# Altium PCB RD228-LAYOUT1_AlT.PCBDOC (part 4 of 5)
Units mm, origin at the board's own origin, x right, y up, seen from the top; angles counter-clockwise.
Board outline 130 x 73 mm, 4 copper layers (TOP, Mid-Layer 1, Mid-Layer 2, BOTTOM), stack 0.711 mm thick; 225 components, 171 nets, 818 pads, 538 vias.
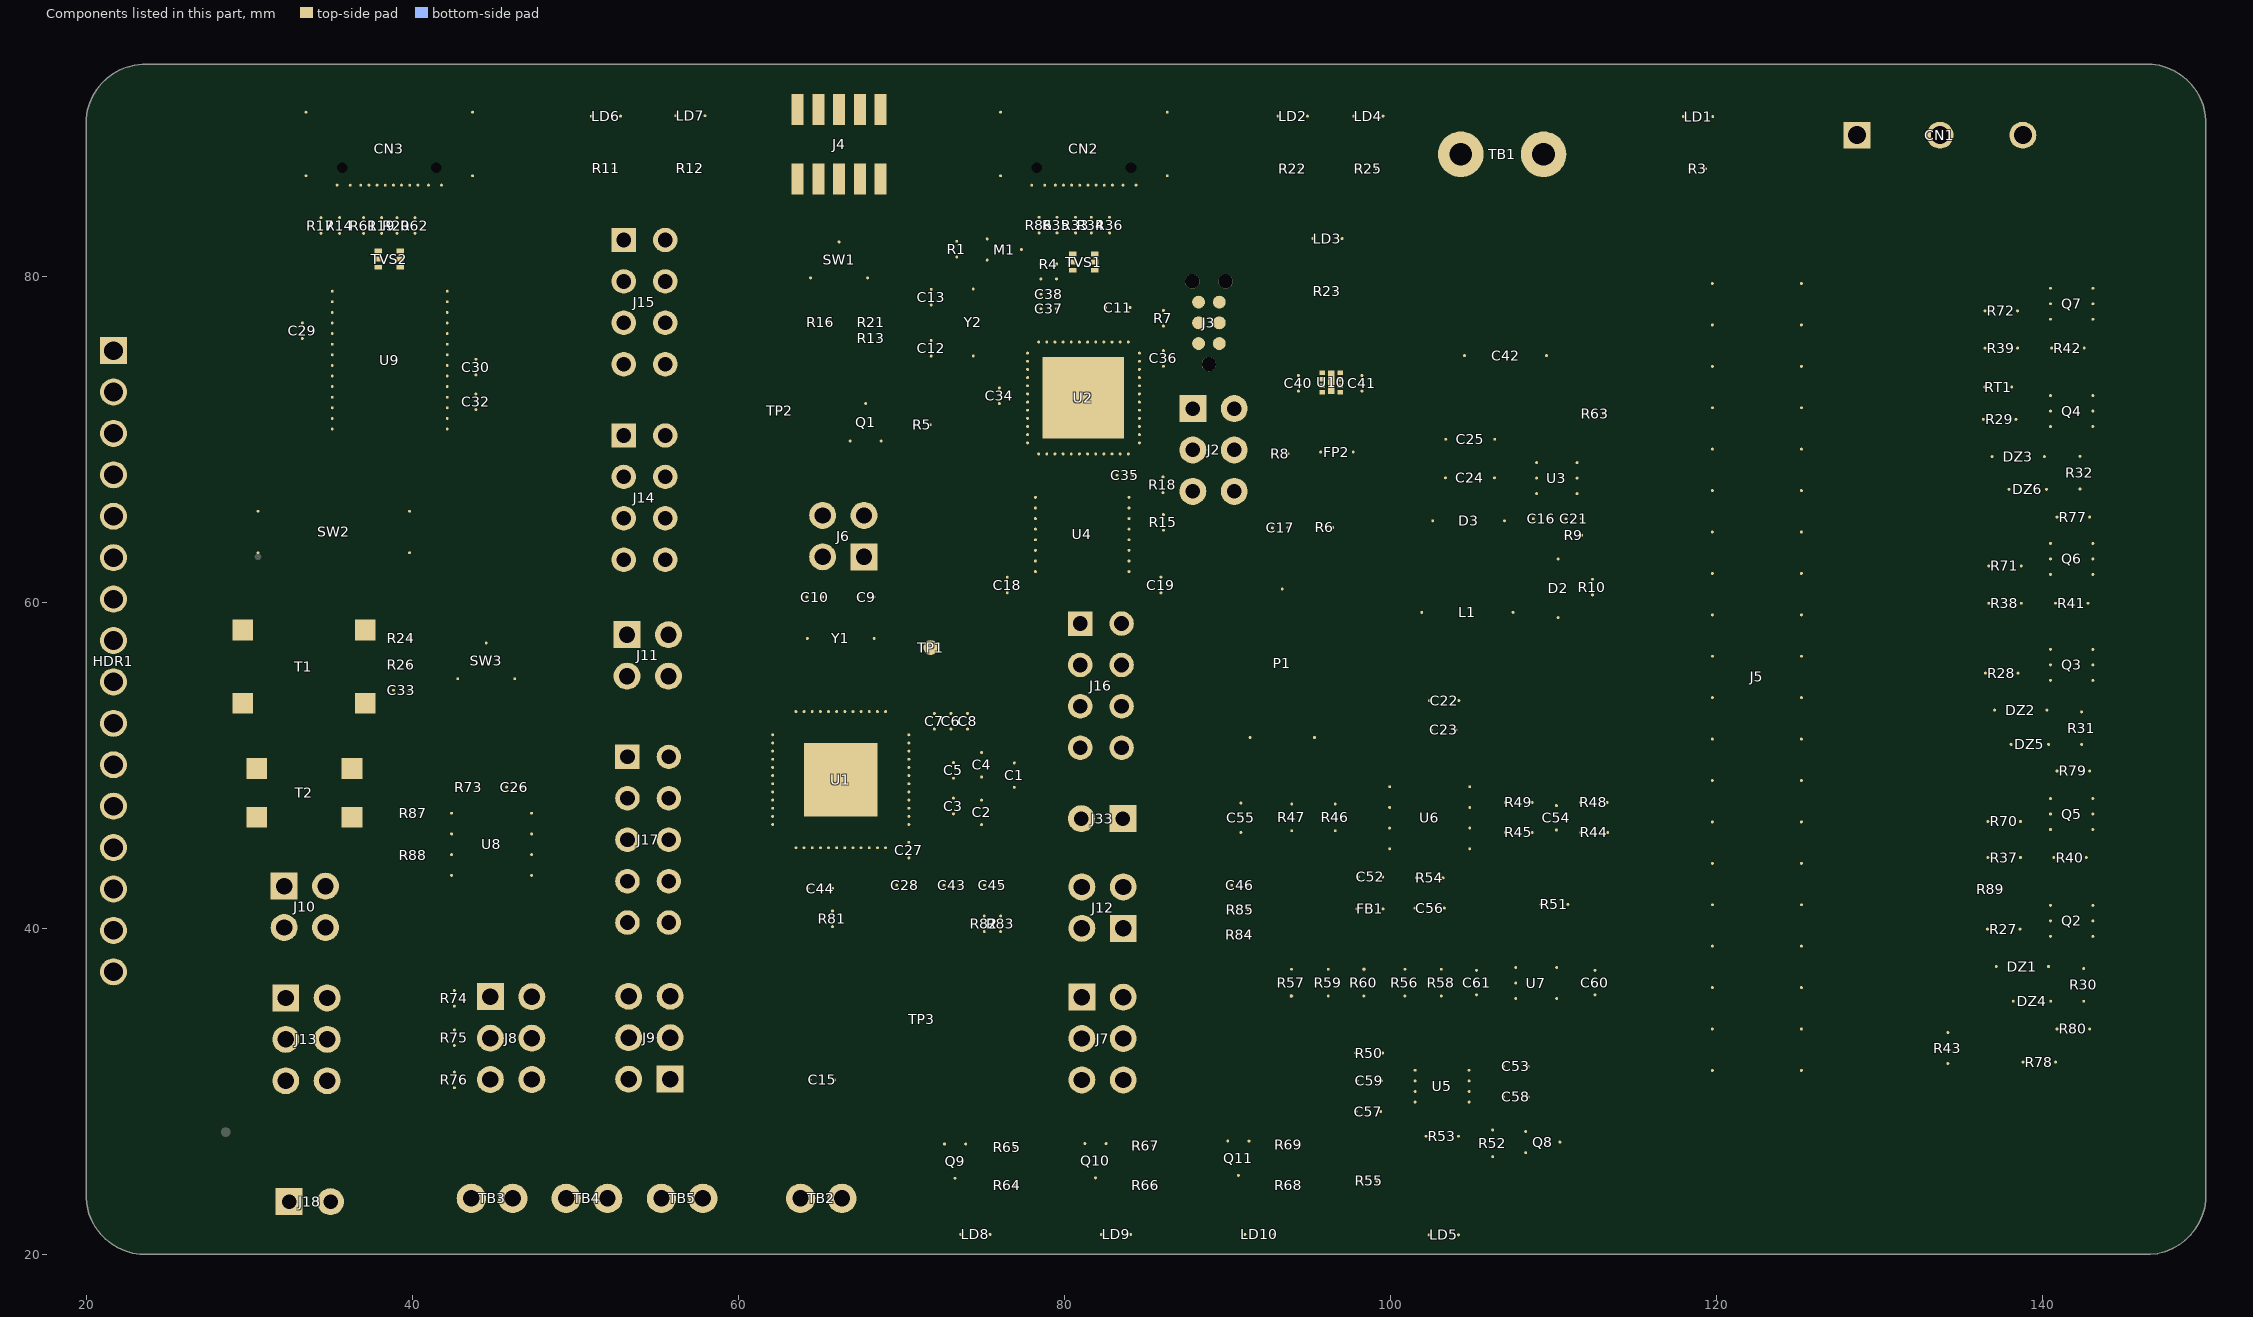
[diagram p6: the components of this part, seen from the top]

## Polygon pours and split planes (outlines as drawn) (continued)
no net on Top Overlay "TOPOVERLAY694" (solid, pour order 0): 274 vertices, not listed, extent 97.347,26.775 98.21,27.784
no net on Top Overlay "TOPOVERLAY693" (solid, pour order 0): 200 vertices, not listed, extent 98.32,26.775 98.968,27.755
no net on Top Overlay "TOPOVERLAY692" (solid, pour order 0): 94 vertices, not listed, extent 99.087,26.791 99.719,27.755
no net on Top Overlay "TOPOVERLAY691" (solid, pour order 0): 220 vertices, not listed, extent 98.149,34.039 98.793,35.035
no net on Top Overlay "TOPOVERLAY690" (solid, pour order 0): 151 vertices, not listed, extent 98.912,34.039 99.548,35.035
no net on Top Overlay "TOPOVERLAY689" (solid, pour order 0): 119 vertices, not listed, extent 97.22,34.055 98.078,35.032
no net on Top Overlay "TOPOVERLAY688" (solid, pour order 0): 274 vertices, not listed, extent 96.975,71.355 97.838,72.365
no net on Top Overlay "TOPOVERLAY687" (solid, pour order 0): 98.333,71.371 98.333,71.604 97.909,71.604 97.909,71.714 98.355,72.347 98.453,72.347 98.453,71.714 98.584,71.714 98.584,71.604 98.453,71.604 98.453,71.371
no net on Top Overlay "TOPOVERLAY686" (solid, pour order 0): 48 vertices, not listed, extent 98.799,71.371 99.158,72.351
no net on Top Overlay "TOPOVERLAY685" (solid, pour order 0): 274 vertices, not listed, extent 96.864,87.554 97.87,88.731
no net on Top Overlay "TOPOVERLAY684" (solid, pour order 0): 42 vertices, not listed, extent 99.287,87.573 100.375,88.711
no net on Top Overlay "TOPOVERLAY683" (solid, pour order 0): 165 vertices, not listed, extent 98.01,87.554 99.099,88.731
no net on Top Overlay "TOPOVERLAY682" (solid, pour order 0): 216 vertices, not listed, extent 97.292,67.075 97.937,68.055
no net on Top Overlay "TOPOVERLAY681" (solid, pour order 0): 95.62,67.075 95.62,68.052 96.279,68.052 96.279,67.936 95.749,67.936 95.749,67.634 96.207,67.634 96.207,67.519 95.749,67.519 95.749,67.075
no net on Top Overlay "TOPOVERLAY680" (solid, pour order 0): 75 vertices, not listed, extent 96.446,67.075 97.192,68.052
no net on Top Overlay "TOPOVERLAY679" (solid, pour order 0): 220 vertices, not listed, extent 97.154,48.415 97.799,49.412
no net on Top Overlay "TOPOVERLAY678" (solid, pour order 0): 119 vertices, not listed, extent 95.467,48.432 96.325,49.408
no net on Top Overlay "TOPOVERLAY677" (solid, pour order 0): 96.786,48.432 96.786,48.665 96.362,48.665 96.362,48.775 96.807,49.408 96.906,49.408 96.906,48.775 97.037,48.775 97.037,48.665 96.906,48.665 96.906,48.432
no net on Top Overlay "TOPOVERLAY676" (solid, pour order 0): 220 vertices, not listed, extent 96.117,65.129 96.761,66.125
no net on Top Overlay "TOPOVERLAY675" (solid, pour order 0): 119 vertices, not listed, extent 95.188,65.145 96.046,66.121
no net on Top Overlay "TOPOVERLAY674" (solid, pour order 0): 148 vertices, not listed, extent 95.162,74.628 95.93,75.621
no net on Top Overlay "TOPOVERLAY673" (solid, pour order 0): 151 vertices, not listed, extent 96.854,74.628 97.49,75.625
no net on Top Overlay "TOPOVERLAY672" (solid, pour order 0): 48 vertices, not listed, extent 96.188,74.644 96.547,75.625
no net on Top Overlay "TOPOVERLAY671" (solid, pour order 0): 241 vertices, not listed, extent 96.753,38.306 97.395,39.303
no net on Top Overlay "TOPOVERLAY670" (solid, pour order 0): 119 vertices, not listed, extent 95.061,38.322 95.919,39.299
no net on Top Overlay "TOPOVERLAY669" (solid, pour order 0): 200 vertices, not listed, extent 95.994,38.306 96.642,39.286
no net on Top Overlay "TOPOVERLAY668" (solid, pour order 0): 312 vertices, not listed, extent 96.652,77.524 97.291,78.521
no net on Top Overlay "TOPOVERLAY667" (solid, pour order 0): 119 vertices, not listed, extent 94.959,77.54 95.817,78.517
no net on Top Overlay "TOPOVERLAY666" (solid, pour order 0): 216 vertices, not listed, extent 95.877,77.54 96.522,78.521
no net on Top Overlay "TOPOVERLAY665" (solid, pour order 0): 48 vertices, not listed, extent 96.714,40.685 97.073,41.665
no net on Top Overlay "TOPOVERLAY664" (solid, pour order 0): 94.934,40.685 94.934,41.661 95.593,41.661 95.593,41.546 95.063,41.546 95.063,41.244 95.522,41.244 95.522,41.129 95.063,41.129 95.063,40.685
no net on Top Overlay "TOPOVERLAY663" (solid, pour order 0): 117 vertices, not listed, extent 95.756,40.685 96.493,41.661
no net on Top Overlay "TOPOVERLAY662" (solid, pour order 0): 274 vertices, not listed, extent 94.807,42.573 95.67,43.583
no net on Top Overlay "TOPOVERLAY661" (solid, pour order 0): 200 vertices, not listed, extent 95.78,42.573 96.428,43.554
no net on Top Overlay "TOPOVERLAY660" (solid, pour order 0): 216 vertices, not listed, extent 96.523,42.59 97.168,43.57
no net on Top Overlay "TOPOVERLAY659" (solid, pour order 0): 312 vertices, not listed, extent 94.731,80.201 95.37,81.197
no net on Top Overlay "TOPOVERLAY658" (solid, pour order 0): 312 vertices, not listed, extent 95.868,80.201 96.507,81.197
no net on Top Overlay "TOPOVERLAY657" (solid, pour order 0): 95.556,80.217 95.556,80.353 95.692,80.353 95.692,80.217
no net on Top Overlay "TOPOVERLAY656" (solid, pour order 0): 30 vertices, not listed, extent 96.575,80.217 97.468,81.194
no net on Top Overlay "TOPOVERLAY655" (solid, pour order 0): 200 vertices, not listed, extent 95.656,31.88 96.304,32.86
no net on Top Overlay "TOPOVERLAY654" (solid, pour order 0): 151 vertices, not listed, extent 96.415,31.88 97.051,32.876
no net on Top Overlay "TOPOVERLAY653" (solid, pour order 0): 119 vertices, not listed, extent 94.723,31.896 95.581,32.873
no net on Top Overlay "TOPOVERLAY652" (solid, pour order 0): 274 vertices, not listed, extent 94.68,30.178 95.543,31.188
no net on Top Overlay "TOPOVERLAY651" (solid, pour order 0): 200 vertices, not listed, extent 95.653,30.178 96.301,31.158
no net on Top Overlay "TOPOVERLAY650" (solid, pour order 0): 241 vertices, not listed, extent 96.412,30.178 97.054,31.175
no net on Top Overlay "TOPOVERLAY649" (solid, pour order 0): 274 vertices, not listed, extent 93.029,71.352 93.892,72.361
no net on Top Overlay "TOPOVERLAY648" (solid, pour order 0): 151 vertices, not listed, extent 94.761,71.352 95.397,72.348
no net on Top Overlay "TOPOVERLAY647" (solid, pour order 0): 94.387,71.368 94.387,71.601 93.963,71.601 93.963,71.711 94.409,72.344 94.507,72.344 94.507,71.711 94.639,71.711 94.639,71.601 94.507,71.601 94.507,71.368
no net on Top Overlay "TOPOVERLAY646" (solid, pour order 0): 216 vertices, not listed, extent 94.553,85.058 95.198,86.039
no net on Top Overlay "TOPOVERLAY645" (solid, pour order 0): 119 vertices, not listed, extent 92.876,85.058 93.735,86.035
no net on Top Overlay "TOPOVERLAY644" (solid, pour order 0): 216 vertices, not listed, extent 93.795,85.058 94.44,86.039
no net on Top Overlay "TOPOVERLAY643" (solid, pour order 0): 94 vertices, not listed, extent 94.5,44.266 95.132,45.23
no net on Top Overlay "TOPOVERLAY642" (solid, pour order 0): 119 vertices, not listed, extent 92.8,44.266 93.658,45.242
no net on Top Overlay "TOPOVERLAY641" (solid, pour order 0): 94.119,44.266 94.119,44.499 93.695,44.499 93.695,44.609 94.14,45.242 94.239,45.242 94.239,44.609 94.37,44.609 94.37,44.499 94.239,44.499 94.239,44.266
no net on Top Overlay "TOPOVERLAY640" (solid, pour order 0): 200 vertices, not listed, extent 93.658,34.064 94.305,35.045
no net on Top Overlay "TOPOVERLAY639" (solid, pour order 0): 119 vertices, not listed, extent 92.724,34.081 93.582,35.057
no net on Top Overlay "TOPOVERLAY638" (solid, pour order 0): 94 vertices, not listed, extent 94.424,34.081 95.056,35.045
no net on Top Overlay "TOPOVERLAY637" (solid, pour order 0): 220 vertices, not listed, extent 93.554,27.257 94.199,28.254
no net on Top Overlay "TOPOVERLAY636" (solid, pour order 0): 119 vertices, not listed, extent 92.625,27.273 93.483,28.25
no net on Top Overlay "TOPOVERLAY635" (solid, pour order 0): 241 vertices, not listed, extent 94.317,27.257 94.959,28.254
no net on Top Overlay "TOPOVERLAY634" (solid, pour order 0): 48 vertices, not listed, extent 93.576,62.63 93.935,63.61
no net on Top Overlay "TOPOVERLAY633" (solid, pour order 0): 75 vertices, not listed, extent 92.622,62.63 93.368,63.607
no net on Top Overlay "TOPOVERLAY632" (solid, pour order 0): 220 vertices, not listed, extent 93.551,24.87 94.196,25.866
no net on Top Overlay "TOPOVERLAY631" (solid, pour order 0): 203 vertices, not listed, extent 94.313,24.87 94.956,25.866
no net on Top Overlay "TOPOVERLAY630" (solid, pour order 0): 119 vertices, not listed, extent 92.622,24.886 93.481,25.862
no net on Top Overlay "TOPOVERLAY629" (solid, pour order 0): 203 vertices, not listed, extent 93.352,69.701 93.995,70.697
no net on Top Overlay "TOPOVERLAY628" (solid, pour order 0): 119 vertices, not listed, extent 92.419,69.717 93.277,70.693
no net on Top Overlay "TOPOVERLAY627" (solid, pour order 0): 94.696,87.548 94.696,88.685 94.85,88.685 95.449,87.792 95.449,88.685 95.593,88.685 95.593,87.548 95.437,87.548 94.84,88.44 94.84,87.548
no net on Top Overlay "TOPOVERLAY626" (solid, pour order 0): 119 vertices, not listed, extent 92.405,87.548 93.405,88.685
no net on Top Overlay "TOPOVERLAY625" (solid, pour order 0): 148 vertices, not listed, extent 93.553,87.529 94.447,88.685
no net on Top Overlay "TOPOVERLAY624" (solid, pour order 0): 274 vertices, not listed, extent 92.038,65.103 92.901,66.113
no net on Top Overlay "TOPOVERLAY623" (solid, pour order 0): 94 vertices, not listed, extent 93.779,65.119 94.41,66.083
no net on Top Overlay "TOPOVERLAY622" (solid, pour order 0): 48 vertices, not listed, extent 93.104,65.119 93.463,66.1
no net on Top Overlay "TOPOVERLAY621" (solid, pour order 0): 200 vertices, not listed, extent 93.578,40.643 94.225,41.623
no net on Top Overlay "TOPOVERLAY620" (solid, pour order 0): 203 vertices, not listed, extent 92.818,40.643 93.461,41.639
no net on Top Overlay "TOPOVERLAY619" (solid, pour order 0): 119 vertices, not listed, extent 91.886,40.659 92.744,41.636
no net on Top Overlay "TOPOVERLAY618" (solid, pour order 0): 312 vertices, not listed, extent 92.946,22.253 93.585,23.25
no net on Top Overlay "TOPOVERLAY617" (solid, pour order 0): 100 vertices, not listed, extent 92.009,22.27 92.817,23.246
no net on Top Overlay "TOPOVERLAY616" (solid, pour order 0): 90.336,22.27 90.336,23.246 90.466,23.246 90.466,22.385 90.946,22.385 90.946,22.27
no net on Top Overlay "TOPOVERLAY615" (solid, pour order 0): 91.102,22.27 91.102,23.246 91.808,23.246 91.808,23.131 91.232,23.131 91.232,22.833 91.772,22.833 91.772,22.717 91.232,22.717 91.232,22.385 91.831,22.385 91.831,22.27
no net on Top Overlay "TOPOVERLAY614" (solid, pour order 0): 203 vertices, not listed, extent 90.609,37.951 91.252,38.947
no net on Top Overlay "TOPOVERLAY613" (solid, pour order 0): 119 vertices, not listed, extent 89.676,37.967 90.534,38.943
no net on Top Overlay "TOPOVERLAY612" (solid, pour order 0): 91.753,37.967 91.753,38.2 91.329,38.2 91.329,38.31 91.774,38.943 91.873,38.943 91.873,38.31 92.004,38.31 92.004,38.2 91.873,38.2 91.873,37.967
no net on Top Overlay "TOPOVERLAY611" (solid, pour order 0): 274 vertices, not listed, extent 89.651,48.644 90.514,49.654
no net on Top Overlay "TOPOVERLAY610" (solid, pour order 0): 200 vertices, not listed, extent 91.382,48.644 92.03,49.624
no net on Top Overlay "TOPOVERLAY609" (solid, pour order 0): 200 vertices, not listed, extent 90.624,48.644 91.272,49.624
no net on Top Overlay "TOPOVERLAY608" (solid, pour order 0): 48 vertices, not listed, extent 91.458,27.781 91.817,28.762
no net on Top Overlay "TOPOVERLAY607" (solid, pour order 0): 202 vertices, not listed, extent 89.549,27.706 90.502,28.775
no net on Top Overlay "TOPOVERLAY606" (solid, pour order 0): 48 vertices, not listed, extent 90.7,27.781 91.059,28.762
no net on Top Overlay "TOPOVERLAY605" (solid, pour order 0): 220 vertices, not listed, extent 91.174,43.259 91.819,44.256
no net on Top Overlay "TOPOVERLAY604" (solid, pour order 0): 274 vertices, not listed, extent 89.447,43.259 90.31,44.269
no net on Top Overlay "TOPOVERLAY603" (solid, pour order 0): 90.806,43.275 90.806,43.509 90.382,43.509 90.382,43.618 90.828,44.252 90.926,44.252 90.926,43.618 91.057,43.618 91.057,43.509 90.926,43.509 90.926,43.275
no net on Top Overlay "TOPOVERLAY602" (solid, pour order 0): 110 vertices, not listed, extent 88.409,64.722 88.946,65.715
no net on Top Overlay "TOPOVERLAY601" (solid, pour order 0): 216 vertices, not listed, extent 89.093,64.738 89.738,65.719
no net on Top Overlay "TOPOVERLAY600" (solid, pour order 0): 312 vertices, not listed, extent 88.931,80.419 89.57,81.416
no net on Top Overlay "TOPOVERLAY599" (solid, pour order 0): 110 vertices, not listed, extent 88.231,80.419 88.768,81.412
no net on Top Overlay "TOPOVERLAY598" (solid, pour order 0): 295 vertices, not listed, extent 89.738,87.526 90.79,88.703
no net on Top Overlay "TOPOVERLAY597" (solid, pour order 0): 100 vertices, not listed, extent 87.568,87.545 88.509,88.683
no net on Top Overlay "TOPOVERLAY596" (solid, pour order 0): 117 vertices, not listed, extent 88.71,87.545 89.569,88.683
no net on Top Overlay "TOPOVERLAY595" (solid, pour order 0): 274 vertices, not listed, extent 87.625,40.541 88.488,41.551
no net on Top Overlay "TOPOVERLAY594" (solid, pour order 0): 75 vertices, not listed, extent 88.647,40.558 89.393,41.534
no net on Top Overlay "TOPOVERLAY593" (solid, pour order 0): 31 vertices, not listed, extent 86.653,40.558 87.547,41.534
no net on Top Overlay "TOPOVERLAY592" (solid, pour order 0): 274 vertices, not listed, extent 86.526,60.607 87.389,61.617
no net on Top Overlay "TOPOVERLAY591" (solid, pour order 0): 48 vertices, not listed, extent 87.592,60.624 87.951,61.604
no net on Top Overlay "TOPOVERLAY590" (solid, pour order 0): 241 vertices, not listed, extent 88.258,60.607 88.9,61.604
no net on Top Overlay "TOPOVERLAY589" (solid, pour order 0): 200 vertices, not listed, extent 87.101,62.868 87.748,63.848
no net on Top Overlay "TOPOVERLAY588" (solid, pour order 0): 119 vertices, not listed, extent 85.409,62.884 86.267,63.861
no net on Top Overlay "TOPOVERLAY587" (solid, pour order 0): 48 vertices, not listed, extent 86.435,62.884 86.794,63.864
no net on Top Overlay "TOPOVERLAY586" (solid, pour order 0): 48 vertices, not listed, extent 87.882,35.198 88.241,36.178
no net on Top Overlay "TOPOVERLAY585" (solid, pour order 0): 100 vertices, not listed, extent 86.853,35.198 87.661,36.175
no net on Top Overlay "TOPOVERLAY584" (solid, pour order 0): 85.18,35.198 85.18,36.175 85.31,36.175 85.31,35.313 85.79,35.313 85.79,35.198
no net on Top Overlay "TOPOVERLAY583" (solid, pour order 0): 85.946,35.198 85.946,36.175 86.652,36.175 86.652,36.059 86.076,36.059 86.076,35.761 86.616,35.761 86.616,35.646 86.076,35.646 86.076,35.313 86.675,35.313 86.675,35.198
no net on Top Overlay "TOPOVERLAY582" (solid, pour order 0): 216 vertices, not listed, extent 87.774,32.607 88.419,33.588
no net on Top Overlay "TOPOVERLAY581" (solid, pour order 0): 100 vertices, not listed, extent 86.853,32.607 87.661,33.584
no net on Top Overlay "TOPOVERLAY580" (solid, pour order 0): 85.18,32.607 85.18,33.584 85.31,33.584 85.31,32.723 85.79,32.723 85.79,32.607
no net on Top Overlay "TOPOVERLAY579" (solid, pour order 0): 85.946,32.607 85.946,33.584 86.652,33.584 86.652,33.469 86.076,33.469 86.076,33.17 86.616,33.17 86.616,33.055 86.076,33.055 86.076,32.723 86.675,32.723 86.675,32.607
no net on Top Overlay "TOPOVERLAY578" (solid, pour order 0): 312 vertices, not listed, extent 87.79,30.102 88.429,31.098
no net on Top Overlay "TOPOVERLAY577" (solid, pour order 0): 100 vertices, not listed, extent 86.853,30.118 87.661,31.095
no net on Top Overlay "TOPOVERLAY576" (solid, pour order 0): 85.18,30.118 85.18,31.095 85.31,31.095 85.31,30.233 85.79,30.233 85.79,30.118
no net on Top Overlay "TOPOVERLAY575" (solid, pour order 0): 85.946,30.118 85.946,31.095 86.652,31.095 86.652,30.979 86.076,30.979 86.076,30.681 86.616,30.681 86.616,30.566 86.076,30.566 86.076,30.233 86.675,30.233 86.675,30.118
no net on Top Overlay "TOPOVERLAY574" (solid, pour order 0): 42 vertices, not listed, extent 86.739,58.16 87.672,59.136
no net on Top Overlay "TOPOVERLAY573" (solid, pour order 0): 75 vertices, not listed, extent 87.879,58.16 88.625,59.136
no net on Top Overlay "TOPOVERLAY572" (solid, pour order 0): 85.248,58.16 85.248,59.021 84.926,59.021 84.926,59.136 85.701,59.136 85.701,59.021 85.378,59.021 85.378,58.16
no net on Top Overlay "TOPOVERLAY571" (solid, pour order 0): 85.836,58.16 85.836,59.136 86.542,59.136 86.542,59.021 85.965,59.021 85.965,58.723 86.506,58.723 86.506,58.608 85.965,58.608 85.965,58.275 86.565,58.275 86.565,58.16
no net on Top Overlay "TOPOVERLAY570" (solid, pour order 0): 87.146,55.62 87.146,56.481 86.824,56.481 86.824,56.596 87.598,56.596 87.598,56.481 87.275,56.481 87.275,55.62
no net on Top Overlay "TOPOVERLAY569" (solid, pour order 0): 165 vertices, not listed, extent 85.797,55.604 86.731,56.613
no net on Top Overlay "TOPOVERLAY568" (solid, pour order 0): 75 vertices, not listed, extent 84.926,55.62 85.672,56.596
no net on Top Overlay "TOPOVERLAY567" (solid, pour order 0): 42 vertices, not listed, extent 86.739,53.08 87.672,54.056
no net on Top Overlay "TOPOVERLAY566" (solid, pour order 0): 75 vertices, not listed, extent 87.879,53.08 88.625,54.056
no net on Top Overlay "TOPOVERLAY565" (solid, pour order 0): 85.248,53.08 85.248,53.941 84.926,53.941 84.926,54.056 85.701,54.056 85.701,53.941 85.378,53.941 85.378,53.08
no net on Top Overlay "TOPOVERLAY564" (solid, pour order 0): 85.836,53.08 85.836,54.056 86.542,54.056 86.542,53.941 85.965,53.941 85.965,53.643 86.506,53.643 86.506,53.528 85.965,53.528 85.965,53.195 86.565,53.195 86.565,53.08
no net on Top Overlay "TOPOVERLAY563" (solid, pour order 0): 87.146,50.54 87.146,51.401 86.824,51.401 86.824,51.516 87.598,51.516 87.598,51.401 87.275,51.401 87.275,50.54
no net on Top Overlay "TOPOVERLAY562" (solid, pour order 0): 165 vertices, not listed, extent 85.797,50.524 86.731,51.533
no net on Top Overlay "TOPOVERLAY561" (solid, pour order 0): 75 vertices, not listed, extent 84.926,50.54 85.672,51.516
no net on Top Overlay "TOPOVERLAY560" (solid, pour order 0): 87.306,46.196 87.306,47.173 87.438,47.173 87.951,46.406 87.951,47.173 88.075,47.173 88.075,46.196 87.942,46.196 87.429,46.962 87.429,46.196
no net on Top Overlay "TOPOVERLAY559" (solid, pour order 0): 84.927,46.196 85.301,47.173 85.441,47.173 85.84,46.196 85.693,46.196 85.58,46.492 85.17,46.492 85.063,46.196
no net on Top Overlay "TOPOVERLAY558" (solid, pour order 0): 86.95,46.196 86.95,47.173 87.08,47.173 87.08,46.196
no net on Top Overlay "TOPOVERLAY557" (solid, pour order 0): 100 vertices, not listed, extent 85.943,46.196 86.75,47.173
no net on Top Overlay "TOPOVERLAY556" (solid, pour order 0): 220 vertices, not listed, extent 85.493,24.87 86.138,25.866
no net on Top Overlay "TOPOVERLAY555" (solid, pour order 0): 220 vertices, not listed, extent 84.735,24.87 85.38,25.866
no net on Top Overlay "TOPOVERLAY554" (solid, pour order 0): 119 vertices, not listed, extent 83.806,24.886 84.664,25.862
no net on Top Overlay "TOPOVERLAY553" (solid, pour order 0): 220 vertices, not listed, extent 84.735,27.232 85.38,28.228
no net on Top Overlay "TOPOVERLAY552" (solid, pour order 0): 119 vertices, not listed, extent 83.806,27.248 84.664,28.224
no net on Top Overlay "TOPOVERLAY551" (solid, pour order 0): 94 vertices, not listed, extent 85.506,27.248 86.138,28.212
no net on Top Overlay "TOPOVERLAY550" (solid, pour order 0): 220 vertices, not listed, extent 85.013,82.632 85.658,83.628
no net on Top Overlay "TOPOVERLAY549" (solid, pour order 0): 312 vertices, not listed, extent 84.26,82.632 84.9,83.628
no net on Top Overlay "TOPOVERLAY548" (solid, pour order 0): 119 vertices, not listed, extent 83.326,82.648 84.184,83.624
no net on Top Overlay "TOPOVERLAY547" (solid, pour order 0): 30 vertices, not listed, extent 83.092,80.283 83.986,81.26
no net on Top Overlay "TOPOVERLAY546" (solid, pour order 0): 371 vertices, not listed, extent 84.058,80.267 84.835,81.277
no net on Top Overlay "TOPOVERLAY545" (solid, pour order 0): 82.607,80.283 82.607,81.144 82.285,81.144 82.285,81.26 83.059,81.26 83.059,81.144 82.736,81.144 82.736,80.283
no net on Top Overlay "TOPOVERLAY544" (solid, pour order 0): 48 vertices, not listed, extent 85.055,80.283 85.414,81.263
no net on Top Overlay "TOPOVERLAY543" (solid, pour order 0): 274 vertices, not listed, extent 82.208,78.87 83.071,79.88
no net on Top Overlay "TOPOVERLAY542" (solid, pour order 0): 48 vertices, not listed, extent 84.033,78.886 84.392,79.866
no net on Top Overlay "TOPOVERLAY541" (solid, pour order 0): 48 vertices, not listed, extent 83.274,78.886 83.633,79.866
no net on Top Overlay "TOPOVERLAY540" (solid, pour order 0): 110 vertices, not listed, extent 81.627,37.265 82.164,38.257
no net on Top Overlay "TOPOVERLAY539" (solid, pour order 0): 93 vertices, not listed, extent 82.335,37.281 82.966,38.245
no net on Top Overlay "TOPOVERLAY538" (solid, pour order 0): 216 vertices, not listed, extent 84.134,22.244 84.778,23.224
no net on Top Overlay "TOPOVERLAY537" (solid, pour order 0): 100 vertices, not listed, extent 83.212,22.244 84.02,23.221
no net on Top Overlay "TOPOVERLAY536" (solid, pour order 0): 81.54,22.244 81.54,23.221 81.669,23.221 81.669,22.359 82.149,22.359 82.149,22.244
no net on Top Overlay "TOPOVERLAY535" (solid, pour order 0): 82.306,22.244 82.306,23.221 83.012,23.221 83.012,23.105 82.435,23.105 82.435,22.807 82.975,22.807 82.975,22.692 82.435,22.692 82.435,22.359 83.034,22.359 83.034,22.244
no net on Top Overlay "TOPOVERLAY534" (solid, pour order 0): 312 vertices, not listed, extent 82.654,48.212 83.293,49.209
no net on Top Overlay "TOPOVERLAY533" (solid, pour order 0): 312 vertices, not listed, extent 81.895,48.212 82.535,49.209
no net on Top Overlay "TOPOVERLAY532" (solid, pour order 0): 110 vertices, not listed, extent 81.195,48.212 81.733,49.205
no net on Top Overlay "TOPOVERLAY531" (solid, pour order 0): 110 vertices, not listed, extent 81.145,44.021 81.682,45.014
no net on Top Overlay "TOPOVERLAY530" (solid, pour order 0): 216 vertices, not listed, extent 82.587,44.037 83.231,45.018
no net on Top Overlay "TOPOVERLAY529" (solid, pour order 0): 48 vertices, not listed, extent 81.936,44.037 82.295,45.018
no net on Top Overlay "TOPOVERLAY528" (solid, pour order 0): 220 vertices, not listed, extent 82.546,59.998 83.191,60.994
no net on Top Overlay "TOPOVERLAY527" (solid, pour order 0): 110 vertices, not listed, extent 81.094,59.998 81.631,60.99
no net on Top Overlay "TOPOVERLAY526" (solid, pour order 0): 48 vertices, not listed, extent 81.885,60.014 82.244,60.994
no net on Top Overlay "TOPOVERLAY525" (solid, pour order 0): 48 vertices, not listed, extent 81.835,27.604 82.194,28.584
no net on Top Overlay "TOPOVERLAY524" (solid, pour order 0): 202 vertices, not listed, extent 80.684,27.528 81.637,28.597
no net on Top Overlay "TOPOVERLAY523" (solid, pour order 0): 151 vertices, not listed, extent 82.501,27.587 83.137,28.584
no net on Top Overlay "TOPOVERLAY522" (solid, pour order 0): 148 vertices, not listed, extent 80.557,66.856 81.325,67.848
no net on Top Overlay "TOPOVERLAY521" (solid, pour order 0): 81.876,66.872 81.876,67.105 81.452,67.105 81.452,67.215 81.898,67.848 81.996,67.848 81.996,67.215 82.127,67.215 82.127,67.105 81.996,67.105 81.996,66.872
no net on Top Overlay "TOPOVERLAY520" (solid, pour order 0): 93 vertices, not listed, extent 79.09,46.247 79.722,47.211
no net on Top Overlay "TOPOVERLAY519" (solid, pour order 0): 165 vertices, not listed, extent 78.03,46.231 78.964,47.241
no net on Top Overlay "TOPOVERLAY518" (solid, pour order 0): 77.713,46.247 77.713,47.224 77.842,47.224 77.842,46.247
no net on Top Overlay "TOPOVERLAY517" (solid, pour order 0): 165 vertices, not listed, extent 77.776,41.888 78.71,42.897
no net on Top Overlay "TOPOVERLAY516" (solid, pour order 0): 203 vertices, not listed, extent 78.826,41.888 79.469,42.884
no net on Top Overlay "TOPOVERLAY515" (solid, pour order 0): 77.459,41.904 77.459,42.88 77.588,42.88 77.588,41.904
no net on Top Overlay "TOPOVERLAY514" (solid, pour order 0): 93 vertices, not listed, extent 78.836,39.364 79.468,40.328
no net on Top Overlay "TOPOVERLAY513" (solid, pour order 0): 165 vertices, not listed, extent 77.776,39.348 78.71,40.357
no net on Top Overlay "TOPOVERLAY512" (solid, pour order 0): 77.459,39.364 77.459,40.34 77.588,40.34 77.588,39.364
no net on Top Overlay "TOPOVERLAY511" (solid, pour order 0): 241 vertices, not listed, extent 78.816,30.127 79.458,31.124
no net on Top Overlay "TOPOVERLAY510" (solid, pour order 0): 165 vertices, not listed, extent 77.764,30.127 78.698,31.137
no net on Top Overlay "TOPOVERLAY509" (solid, pour order 0): 77.447,30.144 77.447,31.12 77.576,31.12 77.576,30.144
no net on Top Overlay "TOPOVERLAY508" (solid, pour order 0): 94 vertices, not listed, extent 78.821,35.224 79.453,36.188
no net on Top Overlay "TOPOVERLAY507" (solid, pour order 0): 165 vertices, not listed, extent 77.761,35.207 78.696,36.217
no net on Top Overlay "TOPOVERLAY506" (solid, pour order 0): 77.444,35.224 77.444,36.2 77.574,36.2 77.574,35.224
no net on Top Overlay "TOPOVERLAY505" (solid, pour order 0): 165 vertices, not listed, extent 77.761,32.667 78.696,33.677
no net on Top Overlay "TOPOVERLAY504" (solid, pour order 0): 203 vertices, not listed, extent 78.812,32.667 79.455,33.664
no net on Top Overlay "TOPOVERLAY503" (solid, pour order 0): 77.444,32.684 77.444,33.66 77.574,33.66 77.574,32.684
no net on Top Overlay "TOPOVERLAY502" (solid, pour order 0): 148 vertices, not listed, extent 76.189,68.1 76.956,69.093
no net on Top Overlay "TOPOVERLAY501" (solid, pour order 0): 216 vertices, not listed, extent 77.107,68.117 77.752,69.097
no net on Top Overlay "TOPOVERLAY500" (solid, pour order 0): 93 vertices, not listed, extent 77.439,56.915 78.071,57.879
no net on Top Overlay "TOPOVERLAY499" (solid, pour order 0): 165 vertices, not listed, extent 76.379,56.899 77.313,57.909
no net on Top Overlay "TOPOVERLAY498" (solid, pour order 0): 76.062,56.915 76.062,57.892 76.191,57.892 76.191,56.915
no net on Top Overlay "TOPOVERLAY497" (solid, pour order 0): 165 vertices, not listed, extent 76.379,51.819 77.313,52.829
no net on Top Overlay "TOPOVERLAY496" (solid, pour order 0): 203 vertices, not listed, extent 77.429,51.819 78.072,52.815
no net on Top Overlay "TOPOVERLAY495" (solid, pour order 0): 76.062,51.835 76.062,52.812 76.191,52.812 76.191,51.835
no net on Top Overlay "TOPOVERLAY494" (solid, pour order 0): 42 vertices, not listed, extent 75.398,83.026 76.332,84.003
no net on Top Overlay "TOPOVERLAY493" (solid, pour order 0): 48 vertices, not listed, extent 76.582,83.026 76.942,84.007
no net on Top Overlay "TOPOVERLAY492" (solid, pour order 0): 220 vertices, not listed, extent 76.254,24.768 76.899,25.764
no net on Top Overlay "TOPOVERLAY491" (solid, pour order 0): 119 vertices, not listed, extent 75.325,24.784 76.183,25.761
no net on Top Overlay "TOPOVERLAY490" (solid, pour order 0): 77.402,24.784 77.402,25.018 76.978,25.018 76.978,25.127 77.423,25.761 77.522,25.761 77.522,25.127 77.653,25.127 77.653,25.018 77.522,25.018 77.522,24.784
no net on Top Overlay "TOPOVERLAY489" (solid, pour order 0): 220 vertices, not listed, extent 76.228,27.105 76.873,28.101
no net on Top Overlay "TOPOVERLAY488" (solid, pour order 0): 119 vertices, not listed, extent 75.3,27.121 76.158,28.097
no net on Top Overlay "TOPOVERLAY487" (solid, pour order 0): 200 vertices, not listed, extent 76.991,27.105 77.639,28.085
no net on Top Overlay "TOPOVERLAY486" (solid, pour order 0): 203 vertices, not listed, extent 75.838,38.179 76.481,39.176
no net on Top Overlay "TOPOVERLAY485" (solid, pour order 0): 312 vertices, not listed, extent 76.599,38.179 77.238,39.176
no net on Top Overlay "TOPOVERLAY484" (solid, pour order 0): 119 vertices, not listed, extent 74.906,38.195 75.764,39.172
no net on Top Overlay "TOPOVERLAY483" (solid, pour order 0): 274 vertices, not listed, extent 74.715,70.666 75.578,71.676
no net on Top Overlay "TOPOVERLAY482" (solid, pour order 0): 312 vertices, not listed, extent 75.69,70.666 76.329,71.662
no net on Top Overlay "TOPOVERLAY481" (solid, pour order 0): 76.832,70.682 76.832,70.915 76.408,70.915 76.408,71.025 76.854,71.658 76.952,71.658 76.952,71.025 77.083,71.025 77.083,70.915 76.952,70.915 76.952,70.682
no net on Top Overlay "TOPOVERLAY480" (solid, pour order 0): 274 vertices, not listed, extent 74.385,43.183 75.248,44.193
no net on Top Overlay "TOPOVERLAY479" (solid, pour order 0): 75.744,43.199 75.744,43.433 75.32,43.433 75.32,43.542 75.765,44.176 75.864,44.176 75.864,43.542 75.995,43.542 75.995,43.433 75.864,43.433 75.864,43.199
no net on Top Overlay "TOPOVERLAY478" (solid, pour order 0): 200 vertices, not listed, extent 76.117,43.183 76.765,44.163
no net on Top Overlay "TOPOVERLAY477" (solid, pour order 0): 274 vertices, not listed, extent 73.623,60.658 74.486,61.668
no net on Top Overlay "TOPOVERLAY476" (solid, pour order 0): 203 vertices, not listed, extent 75.354,60.658 75.997,61.655
no net on Top Overlay "TOPOVERLAY475" (solid, pour order 0): 48 vertices, not listed, extent 74.689,60.674 75.048,61.655
no net on Top Overlay "TOPOVERLAY474" (solid, pour order 0): 36 vertices, not listed, extent 73.522,72.689 74.417,73.665
no net on Top Overlay "TOPOVERLAY473" (solid, pour order 0): 216 vertices, not listed, extent 74.468,72.689 75.113,73.669
no net on Top Overlay "TOPOVERLAY472" (solid, pour order 0): 274 vertices, not listed, extent 73.242,53.8 74.105,54.81
no net on Top Overlay "TOPOVERLAY471" (solid, pour order 0): 203 vertices, not listed, extent 74.215,53.8 74.858,54.797
no net on Top Overlay "TOPOVERLAY470" (solid, pour order 0): 48 vertices, not listed, extent 75.69,22.295 76.049,23.275
no net on Top Overlay "TOPOVERLAY469" (solid, pour order 0): 100 vertices, not listed, extent 74.661,22.295 75.469,23.271
no net on Top Overlay "TOPOVERLAY468" (solid, pour order 0): 72.988,22.295 72.988,23.271 73.118,23.271 73.118,22.41 73.598,22.41 73.598,22.295
no net on Top Overlay "TOPOVERLAY467" (solid, pour order 0): 73.754,22.295 73.754,23.271 74.46,23.271 74.46,23.156 73.884,23.156 73.884,22.858 74.424,22.858 74.424,22.743 73.884,22.743 73.884,22.41 74.483,22.41 74.483,22.295
no net on Top Overlay "TOPOVERLAY466" (solid, pour order 0): 48 vertices, not listed, extent 73.557,82.722 73.916,83.702
no net on Top Overlay "TOPOVERLAY465" (solid, pour order 0): 119 vertices, not listed, extent 72.531,82.722 73.389,83.698
no net on Top Overlay "TOPOVERLAY464" (solid, pour order 0): 202 vertices, not listed, extent 72.429,27.528 73.382,28.597
no net on Top Overlay "TOPOVERLAY463" (solid, pour order 0): 241 vertices, not listed, extent 73.488,27.587 74.13,28.584
no net on Top Overlay "TOPOVERLAY462" (solid, pour order 0): 274 vertices, not listed, extent 72.201,87.582 73.064,88.592
no net on Top Overlay "TOPOVERLAY461" (solid, pour order 0): 73.222,87.598 73.222,88.575 73.354,88.575 73.868,87.808 73.868,88.575 73.992,88.575 73.992,87.598 73.858,87.598 73.346,88.364 73.346,87.598
no net on Top Overlay "TOPOVERLAY460" (solid, pour order 0): 216 vertices, not listed, extent 74.144,87.598 74.789,88.579
no net on Top Overlay "TOPOVERLAY459" (solid, pour order 0): 203 vertices, not listed, extent 73.006,39.779 73.649,40.776
no net on Top Overlay "TOPOVERLAY458" (solid, pour order 0): 119 vertices, not listed, extent 72.074,39.796 72.932,40.772
no net on Top Overlay "TOPOVERLAY457" (solid, pour order 0): 216 vertices, not listed, extent 73.75,39.796 74.395,40.776
no net on Top Overlay "TOPOVERLAY456" (solid, pour order 0): 274 vertices, not listed, extent 71.998,41.151 72.861,42.161
no net on Top Overlay "TOPOVERLAY455" (solid, pour order 0): 312 vertices, not listed, extent 73.73,41.151 74.369,42.147
no net on Top Overlay "TOPOVERLAY454" (solid, pour order 0): 73.356,41.167 73.356,41.401 72.932,41.401 72.932,41.51 73.378,42.144 73.476,42.144 73.476,41.51 73.607,41.51 73.607,41.401 73.476,41.401 73.476,41.167
no net on Top Overlay "TOPOVERLAY453" (solid, pour order 0): 274 vertices, not listed, extent 72.207,44.961 73.07,45.971
no net on Top Overlay "TOPOVERLAY452" (solid, pour order 0): 75 vertices, not listed, extent 73.229,44.977 73.975,45.954
no net on Top Overlay "TOPOVERLAY451" (solid, pour order 0): 30 vertices, not listed, extent 71.236,44.977 72.129,45.954
no net on Top Overlay "TOPOVERLAY450" (solid, pour order 0): 274 vertices, not listed, extent 71.169,53.724 72.032,54.734
no net on Top Overlay "TOPOVERLAY449" (solid, pour order 0): 94 vertices, not listed, extent 72.151,53.74 72.782,54.704
no net on Top Overlay "TOPOVERLAY448" (solid, pour order 0): 48 vertices, not listed, extent 72.563,58.007 72.922,58.988
no net on Top Overlay "TOPOVERLAY447" (solid, pour order 0): 71.024,58.007 71.024,58.869 70.702,58.869 70.702,58.984 71.477,58.984 71.477,58.869 71.154,58.869 71.154,58.007
no net on Top Overlay "TOPOVERLAY446" (solid, pour order 0): 75 vertices, not listed, extent 71.609,58.007 72.355,58.984
no net on Top Overlay "TOPOVERLAY445" (solid, pour order 0): 200 vertices, not listed, extent 71.511,71.383 72.159,72.363
no net on Top Overlay "TOPOVERLAY444" (solid, pour order 0): 119 vertices, not listed, extent 70.578,71.399 71.436,72.375
no net on Top Overlay "TOPOVERLAY443" (solid, pour order 0): 110 vertices, not listed, extent 69.892,87.608 70.43,88.6
no net on Top Overlay "TOPOVERLAY442" (solid, pour order 0): 70.976,87.624 70.976,87.857 70.552,87.857 70.552,87.967 70.998,88.6 71.096,88.6 71.096,87.967 71.228,87.967 71.228,87.857 71.096,87.857 71.096,87.624
no net on Top Overlay "TOPOVERLAY441" (solid, pour order 0): 214 vertices, not listed, extent 69.861,35.934 70.724,37.436
no net on Top Overlay "TOPOVERLAY440" (solid, pour order 0): 29 vertices, not listed, extent 70.901,35.962 71.719,37.389
no net on Top Overlay "TOPOVERLAY439" (solid, pour order 0): 71 vertices, not listed, extent 71.914,35.965 72.778,37.393
no net on Top Overlay "TOPOVERLAY438" (solid, pour order 0): 274 vertices, not listed, extent 71.561,64.697 72.424,65.707
no net on Top Overlay "TOPOVERLAY437" (solid, pour order 0): 371 vertices, not listed, extent 69.357,64.697 70.134,65.707
no net on Top Overlay "TOPOVERLAY436" (solid, pour order 0): 73.336,64.713 73.336,65.689 73.466,65.689 73.466,65.205 73.949,65.689 74.125,65.689 73.715,65.293 74.143,64.713 73.972,64.713 73.625,65.205 73.466,65.051 73.466,64.713
no net on Top Overlay "TOPOVERLAY435" (solid, pour order 0): 72.578,64.713 72.578,65.689 72.707,65.689 72.707,64.828 73.187,64.828 73.187,64.713
no net on Top Overlay "TOPOVERLAY434" (solid, pour order 0): 96 vertices, not listed, extent 70.221,64.713 71.478,65.689
no net on Top Overlay "TOPOVERLAY433" (solid, pour order 0): 96 vertices, not listed, extent 70.221,62.122 71.478,63.099
no net on Top Overlay "TOPOVERLAY432" (solid, pour order 0): 371 vertices, not listed, extent 69.357,62.106 70.134,63.116
no net on Top Overlay "TOPOVERLAY431" (solid, pour order 0): 165 vertices, not listed, extent 72.923,62.106 73.857,63.116
no net on Top Overlay "TOPOVERLAY430" (solid, pour order 0): 72.606,62.122 72.606,63.099 72.735,63.099 72.735,62.122
no net on Top Overlay "TOPOVERLAY429" (solid, pour order 0): 100 vertices, not listed, extent 71.598,62.122 72.405,63.099
no net on Top Overlay "TOPOVERLAY428" (solid, pour order 0): 274 vertices, not listed, extent 69.028,41.156 69.891,42.166
no net on Top Overlay "TOPOVERLAY427" (solid, pour order 0): 203 vertices, not listed, extent 70.759,41.156 71.402,42.152
no net on Top Overlay "TOPOVERLAY426" (solid, pour order 0): 216 vertices, not listed, extent 69.987,41.172 70.632,42.152
no net on Top Overlay "TOPOVERLAY425" (solid, pour order 0): 371 vertices, not listed, extent 69.026,80.597 69.802,81.607
no net on Top Overlay "TOPOVERLAY424" (solid, pour order 0): 96 vertices, not listed, extent 69.89,80.613 71.146,81.59
no net on Top Overlay "TOPOVERLAY423" (solid, pour order 0): 48 vertices, not listed, extent 71.31,80.613 71.669,81.594
no net on Top Overlay "TOPOVERLAY422" (solid, pour order 0): 274 vertices, not listed, extent 68.835,59.795 69.698,60.804
no net on Top Overlay "TOPOVERLAY421" (solid, pour order 0): 241 vertices, not listed, extent 69.808,59.795 70.45,60.791
no net on Top Overlay "TOPOVERLAY420" (solid, pour order 0): 48 vertices, not listed, extent 68.221,73.095 68.58,74.075
no net on Top Overlay "TOPOVERLAY419" (solid, pour order 0): 202 vertices, not listed, extent 67.07,73.02 68.023,74.089
no net on Top Overlay "TOPOVERLAY418" (solid, pour order 0): 67.146,77.988 67.146,78.964 67.278,78.964 67.792,78.197 67.792,78.964 67.916,78.964 67.916,77.988 67.782,77.988 67.27,78.753 67.27,77.988
no net on Top Overlay "TOPOVERLAY417" (solid, pour order 0): 68.38,77.988 68.38,78.849 68.058,78.849 68.058,78.964 68.833,78.964 68.833,78.849 68.51,78.849 68.51,77.988
no net on Top Overlay "TOPOVERLAY416" (solid, pour order 0): 66.791,77.988 66.791,78.964 66.92,78.964 66.92,77.988
no net on Top Overlay "TOPOVERLAY415" (solid, pour order 0): 220 vertices, not listed, extent 66.269,66.932 66.914,67.928
no net on Top Overlay "TOPOVERLAY414" (solid, pour order 0): 110 vertices, not listed, extent 65.574,66.932 66.112,67.925
no net on Top Overlay "TOPOVERLAY413" (solid, pour order 0): 295 vertices, not listed, extent 65.14,26.927 66.043,27.937
no net on Top Overlay "TOPOVERLAY412" (solid, pour order 0): 66.232,26.943 66.232,27.92 66.365,27.92 66.878,27.153 66.878,27.92 67.002,27.92 67.002,26.943 66.868,26.943 66.356,27.709 66.356,26.943
no net on Top Overlay "TOPOVERLAY411" (solid, pour order 0): 100 vertices, not listed, extent 67.218,26.943 68.026,27.92
no net on Top Overlay "TOPOVERLAY410" (solid, pour order 0): 203 vertices, not listed, extent 65.615,38.56 66.258,39.557
no net on Top Overlay "TOPOVERLAY409" (solid, pour order 0): 119 vertices, not listed, extent 64.682,38.576 65.541,39.553
no net on Top Overlay "TOPOVERLAY408" (solid, pour order 0): 48 vertices, not listed, extent 66.467,38.576 66.826,39.557
no net on Top Overlay "TOPOVERLAY407" (solid, pour order 0): 274 vertices, not listed, extent 63.946,31.55 64.809,32.56
no net on Top Overlay "TOPOVERLAY406" (solid, pour order 0): 200 vertices, not listed, extent 65.678,31.55 66.325,32.53
no net on Top Overlay "TOPOVERLAY405" (solid, pour order 0): 48 vertices, not listed, extent 65.012,31.566 65.371,32.546
no net on Top Overlay "TOPOVERLAY404" (solid, pour order 0): 220 vertices, not listed, extent 65.582,75.644 66.227,76.641
no net on Top Overlay "TOPOVERLAY403" (solid, pour order 0): 119 vertices, not listed, extent 63.895,75.66 64.753,76.637
no net on Top Overlay "TOPOVERLAY402" (solid, pour order 0): 48 vertices, not listed, extent 64.921,75.66 65.28,76.641
no net on Top Overlay "TOPOVERLAY401" (solid, pour order 0): 50 vertices, not listed, extent 63.763,77.988 64.658,78.964
no net on Top Overlay "TOPOVERLAY400" (solid, pour order 0): 65.02,77.988 65.02,78.849 64.698,78.849 64.698,78.964 65.473,78.964 65.473,78.849 65.15,78.849 65.15,77.988
no net on Top Overlay "TOPOVERLAY399" (solid, pour order 0): 62.955,77.988 62.955,78.964 63.661,78.964 63.661,78.849 63.085,78.849 63.085,78.55 63.625,78.55 63.625,78.435 63.085,78.435 63.085,78.103 63.684,78.103 63.684,77.988
no net on Top Overlay "TOPOVERLAY398" (solid, pour order 0): 165 vertices, not listed, extent 64.455,83.34 65.39,84.35
no net on Top Overlay "TOPOVERLAY397" (solid, pour order 0): 66.512,83.34 66.794,84.35 66.891,84.35 66.608,83.34
no net on Top Overlay "TOPOVERLAY396" (solid, pour order 0): 295 vertices, not listed, extent 68.858,83.34 69.761,84.35
no net on Top Overlay "TOPOVERLAY395" (solid, pour order 0): 295 vertices, not listed, extent 65.523,83.34 66.426,84.35
no net on Top Overlay "TOPOVERLAY394" (solid, pour order 0): 100 vertices, not listed, extent 66.995,83.357 67.803,84.333
no net on Top Overlay "TOPOVERLAY393" (solid, pour order 0): 117 vertices, not listed, extent 67.976,83.357 68.713,84.333
no net on Top Overlay "TOPOVERLAY392" (solid, pour order 0): 75 vertices, not listed, extent 62.6,83.357 63.345,84.333
no net on Top Overlay "TOPOVERLAY391" (solid, pour order 0): 119 vertices, not listed, extent 63.512,83.357 64.37,84.333
no net on Top Overlay "TOPOVERLAY390" (solid, pour order 0): 63.436,26.969 63.436,27.945 63.568,27.945 64.082,27.178 64.082,27.945 64.206,27.945 64.206,26.969 64.072,26.969 63.56,27.734 63.56,26.969
no net on Top Overlay "TOPOVERLAY389" (solid, pour order 0): 63.081,26.969 63.081,27.945 63.21,27.945 63.21,26.969
no net on Top Overlay "TOPOVERLAY388" (solid, pour order 0): 62.295,26.969 62.295,27.945 62.424,27.945 62.424,27.084 62.904,27.084 62.904,26.969
no net on Top Overlay "TOPOVERLAY387" (solid, pour order 0): 274 vertices, not listed, extent 61.33,59.769 62.193,60.779
no net on Top Overlay "TOPOVERLAY386" (solid, pour order 0): 151 vertices, not listed, extent 63.061,59.769 63.698,60.766
no net on Top Overlay "TOPOVERLAY385" (solid, pour order 0): 48 vertices, not listed, extent 62.396,59.785 62.755,60.766
no net on Top Overlay "TOPOVERLAY384" (solid, pour order 0): 36 vertices, not listed, extent 61.33,57.144 62.225,58.12
no net on Top Overlay "TOPOVERLAY383" (solid, pour order 0): 48 vertices, not listed, extent 62.384,57.144 62.743,58.124
no net on Top Overlay "TOPOVERLAY382" (solid, pour order 0): 148 vertices, not listed, extent 61.279,52.632 62.047,53.624
no net on Top Overlay "TOPOVERLAY381" (solid, pour order 0): 48 vertices, not listed, extent 62.305,52.648 62.664,53.628
no net on Top Overlay "TOPOVERLAY380" (solid, pour order 0): 274 vertices, not listed, extent 61.203,41.888 62.066,42.897
no net on Top Overlay "TOPOVERLAY379" (solid, pour order 0): 62.561,41.904 62.561,42.137 62.137,42.137 62.137,42.247 62.583,42.88 62.681,42.88 62.681,42.247 62.812,42.247 62.812,42.137 62.681,42.137 62.681,41.904
no net on Top Overlay "TOPOVERLAY378" (solid, pour order 0): 63.319,41.904 63.319,42.137 62.895,42.137 62.895,42.247 63.341,42.88 63.439,42.88 63.439,42.247 63.571,42.247 63.571,42.137 63.439,42.137 63.439,41.904
no net on Top Overlay "TOPOVERLAY377" (solid, pour order 0): 214 vertices, not listed, extent 61.148,73.272 62.012,74.774
no net on Top Overlay "TOPOVERLAY376" (solid, pour order 0): 29 vertices, not listed, extent 62.188,73.3 63.006,74.727
no net on Top Overlay "TOPOVERLAY375" (solid, pour order 0): 71 vertices, not listed, extent 63.202,73.303 64.065,74.731
no net on Top Overlay "TOPOVERLAY374" (solid, pour order 0): 48 vertices, not listed, extent 63.093,64.713 63.452,65.693
no net on Top Overlay "TOPOVERLAY373" (solid, pour order 0): 48 vertices, not listed, extent 62.335,64.713 62.694,65.693
no net on Top Overlay "TOPOVERLAY372" (solid, pour order 0): 165 vertices, not listed, extent 61.191,64.697 62.125,65.707
no net on Top Overlay "TOPOVERLAY371" (solid, pour order 0): 60.874,64.713 60.874,65.689 61.003,65.689 61.003,64.713
no net on Top Overlay "TOPOVERLAY370" (solid, pour order 0): 48 vertices, not listed, extent 62.149,62.173 62.508,63.153
no net on Top Overlay "TOPOVERLAY369" (solid, pour order 0): 165 vertices, not listed, extent 61.005,62.157 61.939,63.167
no net on Top Overlay "TOPOVERLAY368" (solid, pour order 0): 152 vertices, not listed, extent 62.815,62.157 63.451,63.153
no net on Top Overlay "TOPOVERLAY367" (solid, pour order 0): 60.688,62.173 60.688,63.149 60.817,63.149 60.817,62.173
no net on Top Overlay "TOPOVERLAY366" (solid, pour order 0): 216 vertices, not listed, extent 58.975,35.325 59.62,36.305
no net on Top Overlay "TOPOVERLAY365" (solid, pour order 0): 165 vertices, not listed, extent 57.938,35.309 58.873,36.319
no net on Top Overlay "TOPOVERLAY364" (solid, pour order 0): 57.621,35.325 57.621,36.302 57.751,36.302 57.751,35.325
no net on Top Overlay "TOPOVERLAY363" (solid, pour order 0): 48 vertices, not listed, extent 59.082,32.734 59.442,33.715
no net on Top Overlay "TOPOVERLAY362" (solid, pour order 0): 165 vertices, not listed, extent 57.938,32.718 58.873,33.728
no net on Top Overlay "TOPOVERLAY361" (solid, pour order 0): 57.621,32.734 57.621,33.711 57.751,33.711 57.751,32.734
no net on Top Overlay "TOPOVERLAY360" (solid, pour order 0): 57.621,30.245 57.621,31.222 57.751,31.222 57.751,30.245
no net on Top Overlay "TOPOVERLAY359" (solid, pour order 0): 165 vertices, not listed, extent 57.938,30.229 58.873,31.239
no net on Top Overlay "TOPOVERLAY358" (solid, pour order 0): 152 vertices, not listed, extent 58.99,30.229 59.626,31.225
no net on Top Overlay "TOPOVERLAY357" (solid, pour order 0): 59.092,47.466 59.092,47.7 58.668,47.7 58.668,47.809 59.114,48.443 59.212,48.443 59.212,47.809 59.344,47.809 59.344,47.7 59.212,47.7 59.212,47.466
no net on Top Overlay "TOPOVERLAY356" (solid, pour order 0): 165 vertices, not listed, extent 57.656,47.45 58.59,48.46
no net on Top Overlay "TOPOVERLAY355" (solid, pour order 0): 57.338,47.466 57.338,48.443 57.468,48.443 57.468,47.466
no net on Top Overlay "TOPOVERLAY354" (solid, pour order 0): 312 vertices, not listed, extent 58.704,49.99 59.343,50.987
no net on Top Overlay "TOPOVERLAY353" (solid, pour order 0): 165 vertices, not listed, extent 57.651,49.99 58.586,51
no net on Top Overlay "TOPOVERLAY352" (solid, pour order 0): 57.334,50.006 57.334,50.983 57.464,50.983 57.464,50.006
no net on Top Overlay "TOPOVERLAY351" (solid, pour order 0): 220 vertices, not listed, extent 58.698,42.37 59.343,43.367
no net on Top Overlay "TOPOVERLAY350" (solid, pour order 0): 165 vertices, not listed, extent 57.651,42.37 58.586,43.38
no net on Top Overlay "TOPOVERLAY349" (solid, pour order 0): 57.334,42.386 57.334,43.363 57.464,43.363 57.464,42.386
no net on Top Overlay "TOPOVERLAY348" (solid, pour order 0): 94 vertices, not listed, extent 58.712,39.846 59.343,40.81
no net on Top Overlay "TOPOVERLAY347" (solid, pour order 0): 165 vertices, not listed, extent 57.651,39.83 58.586,40.84
no net on Top Overlay "TOPOVERLAY346" (solid, pour order 0): 57.334,39.846 57.334,40.823 57.464,40.823 57.464,39.846
no net on Top Overlay "TOPOVERLAY345" (solid, pour order 0): 200 vertices, not listed, extent 58.696,44.91 59.344,45.89
no net on Top Overlay "TOPOVERLAY344" (solid, pour order 0): 165 vertices, not listed, extent 57.644,44.91 58.579,45.92
no net on Top Overlay "TOPOVERLAY343" (solid, pour order 0): 57.327,44.926 57.327,45.903 57.457,45.903 57.457,44.926
no net on Top Overlay "TOPOVERLAY342" (solid, pour order 0): 165 vertices, not listed, extent 57.634,57.559 58.568,58.569
no net on Top Overlay "TOPOVERLAY341" (solid, pour order 0): 203 vertices, not listed, extent 58.684,57.559 59.327,58.556
no net on Top Overlay "TOPOVERLAY340" (solid, pour order 0): 57.316,57.576 57.316,58.552 57.446,58.552 57.446,57.576
no net on Top Overlay "TOPOVERLAY339" (solid, pour order 0): 241 vertices, not listed, extent 58.685,54.969 59.327,55.965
